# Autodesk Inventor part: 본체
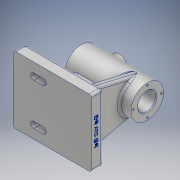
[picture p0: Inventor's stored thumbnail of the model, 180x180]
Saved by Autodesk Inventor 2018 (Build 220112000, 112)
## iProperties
Created: 2022-06
Part Number: 본체
Material: 알루미늄 6061
Document SubType Name: Modeling
Designer: 4강의실
Density: 2.7 g/cm^3
Appearance: 알루미늄 - 평지
Mass: 638.981 g
Surface Area: 521.522 cm^2
Volume: 236.66 cm^3
Author: 4강의실
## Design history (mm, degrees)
sketch "스케치1"
  geometry: L1 (50, -43)-(-50, -43); L2 (-50, -43)-(-50, 43); L3 (-50, 43)-(50, 43); L4 (50, 43)-(50, -43); 1 further point
  constraints: 8 end point, 2 parallel, 1 horizontal, 1 perpendicular
  dimensions: "d0" = 100 distance of L1.start L1.end; "d1" = 86 distance of L1.end L2.end; "d2" = 43 vertical distance of L1.end point (0, 0); "d3" = 50 distance from line of L4 point (0, 0)
extrude "돌출1" new body sketch "스케치1" distance "d4" = 15; taper "d5" = 0 deg
sketch "스케치2"
  geometry: L1 (-59.635, 57)-(61.669, 57); L2 (50, -15)-(-50, -15) reference; L3 (-35, 78)-(-35, 71.5); L4 (-35, 71.5)-(30, 71.5); L5 (30, 71.5)-(30, 68.5); L6 (30, 68.5)-(50, 68.5); L7 (50, 68.5)-(50, 78); L8 (50, 78)-(-35, 78); L9 (50, 0)-(50, -15) reference; 1 further point
  constraints: 14 end point, 5 perpendicular, 1 horizontal, 1 vertical
  dimensions: "d6" = 72 distance between parallel lines of L2 L1; "d7" = 23 diameter of L6 L1; "d8" = 42 diameter of L8 L1; "d9" = 29 diameter of L4 L1; "d10" = 85 distance between parallel lines of L7 L3; "d11" = 0 distance between parallel lines of L9 L7; "d12" = 20 distance of L5.end L6.end
revolve "회전1" sketch "스케치2" stored, may be unused: angle "d13" = 90 deg
node "작업 평면1"
sketch "스케치3"
  geometry: L1 (63.441, 61.814)-(78, 0); L2 (78, 0)-(8, 0); L3 (8, 0)-(22.559, 61.814); L4 (86, 0)-(86, -15) reference; A1 r 21 centre (43, 57) between (63.441, 61.814) and (22.559, 61.814) reference; 2 further points
  constraints: 6 end point, 2 point on circle, 2 tangent, 1 coincident, 1 horizontal, 1 midpoint
  dimensions: "d15" = 8 distance from line of L4 L1.end
extrude "돌출2" join sketch "스케치3" distance "d16" = 10; taper "d17" = 0 deg
sketch "스케치4"
  geometry: L1 (-21.897, 36)-(-35, 0); L2 (-50, 0)-(50, 0) reference; L3 (-50, 0)-(-50, -15) reference; L4 (-35, 36)-(50, 36) reference; 1 further point
  constraints: 2 end point, 2 point on line
  dimensions: "d18" = 15 distance from line of L3 L1.end; "d19" = 70 deg angle of L2 L1
feature "리브1" sketch "스케치4" dims "d20" = 1, "d21" = 10, "d22" = 0, "d23" = 0, "d24" = 1, "d25" = 1
sketch "스케치5"
  geometry: L1 (-24, 27)-(-12, 27); L2 (-24, 34)-(-12, 34); L3 (-12, 20)-(-24, 20); L4 (-50, -43)-(-50, 43) reference; A1 r 7 centre (-24, 27) between (-24, 34) and (-24, 20); A2 r 7 centre (-12, 27) between (-12, 20) and (-12, 34); 2 further points
  constraints: 8 end point, 4 point on circle, 4 tangent, 2 centre point, 1 horizontal, 1 midpoint, 1 parallel
  dimensions: "d26" = 12 distance of L1.end L1.start; "d27" = 26 distance from line of L4 L1.start; "d28" = 27 vertical distance of point (0, 0) L1.start; "d29" = 7 radius of A1
extrude "돌출3" join sketch "스케치5" distance "d30" = 3; taper "d31" = 0 deg
sketch "스케치6"
  geometry: L1 (-24, 27)-(-12, 27); L2 (-24, 23)-(-12, 23); L3 (-12, 31)-(-24, 31); L4 (-50, -43)-(-50, 43) reference; A1 r 4 centre (-24, 27) between (-24, 31) and (-24, 23); A2 r 4 centre (-12, 27) between (-12, 23) and (-12, 31); 2 further points
  constraints: 8 end point, 4 point on circle, 4 tangent, 2 centre point, 1 horizontal, 1 midpoint, 1 parallel
  dimensions: "d32" = 12 distance of L1.start L1.end; "d34" = 27 vertical distance of point (0, 0) point (-18, 27); "d35" = 4 radius of A2; "d36" = 26 distance from line of L4 L1.start
extrude "돌출4" cut sketch "스케치6" extent not by distance; stored distance "d37" = 3; taper "d38" = 0 deg
node "작업 평면2"
sketch "스케치7"
  geometry: L1 (35, 21)-(35, -21) reference; L2 (-50, 43)-(50, 43) reference; C1 r 11 at (10, 0); 1 further point
  constraints: 1 centre point
  dimensions: "d40" = 22 diameter of C1; "d41" = 25 distance from line of L1 C1.centre; "d42" = 43 distance from line of L2 C1.centre
extrude "돌출5" join sketch "스케치7" stored distance "d43" = 3; taper "d44" = 0 deg
sketch "스케치8"
  geometry: C1 r 11 at (10, 0) reference; C2 r 7 at (10, 0); 1 further point
  constraints: 1 centre point, 1 coincident
  dimensions: "d45" = 14 diameter of C2
extrude "돌출6" cut sketch "스케치8" distance "d46" = 4; taper "d47" = 0 deg
sketch "스케치9"
  geometry: C1 r 7 at (0, 0) reference; 1 further point
hole "구멍1" sketch "스케치9" at (0, 0) diameter "d48" = 4.917; stored, may be unused: countersink angle "d52" = 82 deg, drill point angle "d54" = 0 deg; dims "d49" = 12, "d50" = 3.023, "d51" = 2, "d53" = 15
sketch "스케치10"
  geometry: L1 (-43, -57)-(-43, -72) reference; C1 r 21 at (0, 0) reference; 2 further points
  dimensions: "d55" = 43 distance from line of L1 point (0, 18); "d56" = 18 distance of C1.centre point (0, 18)
hole "구멍2" sketch "스케치10" at (0, 18) diameter "d57" = 2.459; stored, may be unused: countersink angle "d61" = 82 deg, drill point angle "d63" = 118 deg; dims "d58" = 8, "d59" = 3.023, "d60" = 2, "d62" = 10
sketch "스케치11"
  geometry: L1 (43, -72)-(-43, -72) reference; L2 (-43, -57)-(-43, -72) reference; 2 further points
  dimensions: "d67" = 90 distance from line of L1 point (0, 18); "d68" = 43 distance from line of L2 point (0, 18)
hole "구멍3" sketch "스케치11" at (0, 18) diameter "d69" = 2.459; stored, may be unused: countersink angle "d73" = 82 deg, drill point angle "d75" = 118 deg; dims "d70" = 8, "d71" = 3.023, "d72" = 2, "d74" = 10
node "작업 평면3"
sketch "스케치12"
  geometry: L1 (86, -15)-(0, -15) reference; L2 (0, 0)-(0, -15) reference; 2 further points
  constraints: 1 other
  dimensions: "d80" = 6 distance from line of L1 point (43, -9); "d81" = 43 distance from line of L2 point (43, -9)
feature "엠보싱1" sketch "스케치12" dims "d0" = 100, "d1" = 86, "d2" = 43, "d3" = 50, "d82" = 0.5, "d83" = 0
chamfer "모따기1" distance "d84" = 1; stored, may be unused: second distance "d85" = 2, angle "d86" = 45 deg
fillet "모깎기2" dims "d88" = 1
fillet "모깎기3" dims "d89" = 3
fillet "모깎기4" dims "d90" = 3
fillet "모깎기5" dims "d91" = 3
fillet "모깎기6" dims "d92" = 3
fillet "모깎기7" dims "d93" = 3
node "솔리드1"
mirror "미러1"
pattern_circular "원형 패턴1" dims angle "d65" = 360 deg
pattern_circular "원형 패턴2" dims angle "d77" = 360 deg
node "투영된 루프1"
other parameters: "d14" = -15, "d39" = 81, "d79" = 38.75
